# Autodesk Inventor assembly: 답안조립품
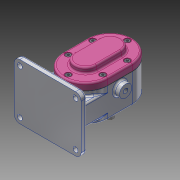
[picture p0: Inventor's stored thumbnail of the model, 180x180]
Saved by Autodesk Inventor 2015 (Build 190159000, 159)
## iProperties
Created: 2020-09
Part Number: 답안조립품
Document SubType Name: Assembly
Designer: LINEART-SSD 16G02
Author: LINEART-SSD 16G02
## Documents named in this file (11)
- C:\Users\LINEART-SSD 16G02\Desktop\700906V1044\답안조립품.iam
- C:\Users\LINEART-SSD 16G02\Desktop\700906V1044\본체.ipt
- C:\Users\LINEART-SSD 16G02\Desktop\700906V1044\개스킷.ipt
- C:\Users\LINEART-SSD 16G02\Desktop\700906V1044\메인축.ipt
- C:\Users\LINEART-SSD 16G02\Desktop\700906V1044\베어링부시.ipt
- C:\Users\LINEART-SSD 16G02\Desktop\700906V1044\볼트 M5.ipt
- C:\Users\LINEART-SSD 16G02\Desktop\700906V1044\서브축.ipt
- C:\Users\LINEART-SSD 16G02\Desktop\700906V1044\스퍼기어.ipt
- C:\Users\LINEART-SSD 16G02\Desktop\700906V1044\오일 실 16 28 7.ipt
- C:\Users\LINEART-SSD 16G02\Desktop\700906V1044\커버.ipt
- C:\Users\LINEART-SSD 16G02\Desktop\700906V1044\키 6 x 6 x 18.ipt
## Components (1 placed, 1 different names)
1. 개스킷:1
